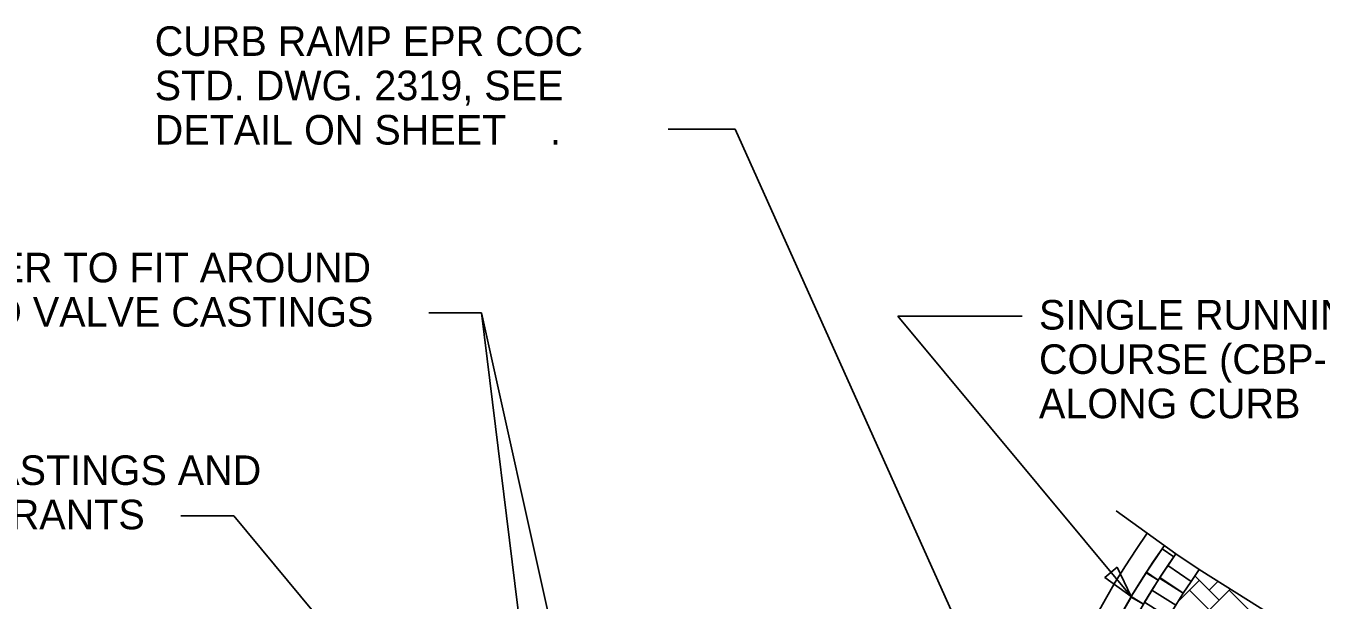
# Model space of a CAD drawing. Extents: x -848 to 1, y -1131 to -115.
# Drawn here: x -814.6 to -753.2, y -783 to -755.8 of the extents above; entities that cross this region are included whole.
import ezdxf

# ---------------------------------------------------------------- set-up
doc = ezdxf.new("R2010")
doc.units = 0
for name, color, linetype in [('PV_P_Curb', 7, 'Continuous'), ('PV_P_Joint', 7, 'Continuous'), ('SC_Scratch3', 7, 'Continuous'), ('TX_X_5', 7, 'Continuous')]:
    doc.layers.add(name, color=color, linetype=linetype)

msp = doc.modelspace()

# ---------------------------------------------------------------- linework, layer by layer
at = {"layer": 'PV_P_Curb'}
for radius, start in [(38, 144.79346), (37, 144.80914)]:
    msp.add_arc((-730.428, -801.735), radius, start, 188.96168, dxfattribs=at)
at = {"layer": 'PV_P_Joint'}
for p, q in [((-760.121, -780.804), (-762.945, -778.768)), ((-758.067, -782.993), (-759.218, -781.842)), ((-760.032, -783.08), (-759.006, -782.054)), ((-758.067, -783.932), (-759.475, -782.524)), ((-758.536, -782.524), (-758.125, -782.112)), ((-758.536, -783.463), (-757.548, -782.475)), ((-756.189, -783.932), (-757.597, -782.524)), ((-759.945, -782.993), (-759.965, -782.973))]:
    msp.add_line(p, q, dxfattribs=at)
for points in [[(-761.516, -781.678), (-760.776, -780.572), (-760.219, -780.945), (-760.959, -782.05)], [(-760.121, -780.804), (-759.02, -781.55), (-759.396, -782.105), (-760.497, -781.359)], [(-760.499, -781.361), (-759.396, -782.105), (-759.771, -782.66), (-760.873, -781.917)], [(-762.229, -782.828), (-761.529, -781.697), (-760.959, -782.05), (-761.66, -783.181)], [(-760.9, -781.958), (-759.771, -782.66), (-760.125, -783.229), (-761.254, -782.526)], [(-761.254, -782.526), (-760.125, -783.229), (-760.479, -783.798), (-761.608, -783.095)], [(-762.897, -784.01), (-762.244, -782.852), (-761.66, -783.181), (-762.313, -784.339)]]:
    msp.add_lwpolyline(points, close=True, dxfattribs=at)
msp.add_lwpolyline([(-751.577, -786.225), (-759.02, -781.55), (-759.396, -782.105), (-759.771, -782.66), (-760.125, -783.229), (-760.479, -783.798), (-760.809, -784.381), (-761.139, -784.964), (-761.449, -785.558), (-761.756, -786.154), (-762.045, -786.758), (-762.323, -787.367), (-762.589, -787.982), (-762.855, -788.597), (-763.102, -789.22), (-763.257, -789.623), (-758.45, -793.967), (-759.36, -804.19), (-764.677, -809.236), (-764.012, -813.452), (-743.604, -810.234)], dxfattribs=at)
at = {"layer": 'SC_Scratch3'}
msp.add_lwpolyline([(-743.604, -810.234), (-764.012, -813.452), (-764.677, -809.236), (-759.36, -804.19), (-758.45, -793.967), (-763.257, -789.623), (-763.102, -789.22), (-762.855, -788.597), (-762.589, -787.982), (-762.323, -787.367), (-762.045, -786.758), (-761.756, -786.154), (-761.449, -785.558), (-761.139, -784.964), (-760.809, -784.381), (-760.479, -783.798), (-760.125, -783.229), (-759.771, -782.66), (-759.396, -782.105), (-759.02, -781.55), (-751.577, -786.225)], dxfattribs=at)
at = {"layer": 'TX_X_5'}
for p, q in [((-784.157, -760.685), (-780.992, -760.685)), ((-764.692, -797), (-780.992, -760.685)), ((-795.498, -769.393), (-792.997, -769.393)), ((-785.078, -805.11), (-792.997, -769.393)), ((-789.743, -795.806), (-792.997, -769.393)), ((-773.289, -769.539), (-767.399, -769.539)), ((-762.229, -782.828), (-773.289, -769.539)), ((-807.239, -778.995), (-804.738, -778.995)), ((-789.719, -797.042), (-804.738, -778.995))]:
    msp.add_line(p, q, dxfattribs=at)
msp.add_lwpolyline([(-762.901, -781.435), (-762.229, -782.828), (-763.477, -781.915)], close=True, dxfattribs=at)

# ---------------------------------------------------------------- texts
for s, p in [('CURB RAMP EPR COC', (-808.479, -757.216)), ('STD. DWG. 2319, SEE', (-808.479, -759.316)), ('DETAIL ON SHEET    .', (-808.479, -761.416)), ('CUT EACH PAVER TO FIT AROUND', (-829.75, -767.942)), ('MANHOLES AND VALVE CASTINGS', (-829.75, -770.042)), ('SINGLE RUNNING', (-766.602, -770.178)), ('COURSE (CBP-P)', (-766.602, -772.278)), ('ALONG CURB', (-766.602, -774.378)), ('VALVE CASTINGS AND', (-824.033, -777.539)), ('FIRE HYDRANTS', (-824.033, -779.639))]:
    msp.add_text(s, height=1.4, dxfattribs=at).set_placement(p)

doc.saveas('drawing.dxf')
